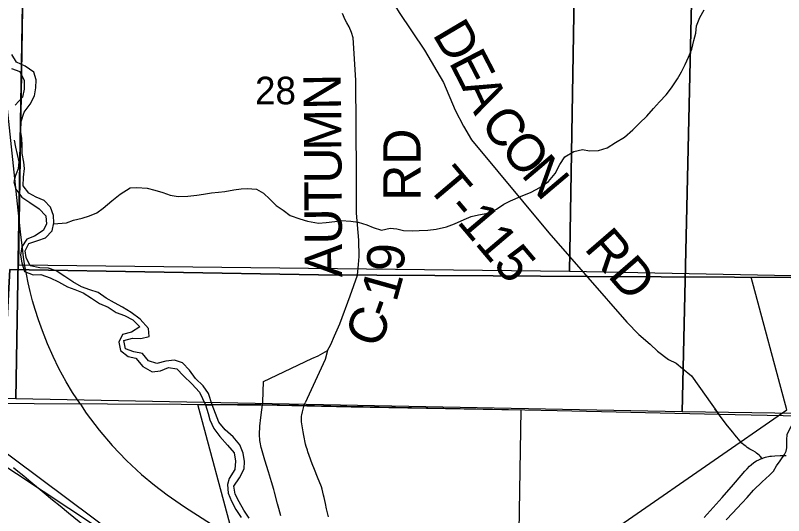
# Model space of a CAD drawing. Extents: x -19.9 to 41.9, y 0 to 32.3.
# Drawn here: x 5.034 to 6.203, y 17.59 to 18.35 of the extents above; entities that cross this region are included whole.
import ezdxf

# ---------------------------------------------------------------- set-up
doc = ezdxf.new("R2010")
doc.units = 0
for name, color, linetype in [('GM_X_City_Street', 7, 'Continuous'), ('GM_X_Corporation', 7, 'Continuous'), ('GM_X_County', 7, 'Continuous'), ('GM_X_County_Road', 7, 'Continuous'), ('GM_X_County_Road_Text', 7, 'Continuous'), ('GM_X_Major_River', 7, 'Continuous'), ('GM_X_Minor_River', 7, 'Continuous'), ('GM_X_Rail_Line', 7, 'Continuous'), ('GM_X_Section', 7, 'Continuous'), ('GM_X_Section_Text', 7, 'Continuous'), ('GM_X_State_Route', 7, 'Continuous'), ('GM_X_Township_Road', 7, 'Continuous'), ('GM_X_Township_Road_Text', 7, 'Continuous'), ('SH_Text', 7, 'Continuous')]:
    doc.layers.add(name, color=color, linetype=linetype)

msp = doc.modelspace()

# ---------------------------------------------------------------- linework, layer by layer
at = {"layer": 'GM_X_City_Street'}
for points in [[(5.4382, 17.5896), (5.4349, 17.6006), (5.4331, 17.6075), (5.4285, 17.6252), (5.4271, 17.6297), (5.4237, 17.6412), (5.4193, 17.6562), (5.4138, 17.674), (5.4085, 17.6919), (5.4081, 17.6935), (5.4064, 17.7012), (5.4061, 17.7039), (5.4057, 17.7131), (5.4061, 17.7256), (5.4078, 17.7391), (5.4108, 17.7622)], [(5.5106, 17.588), (5.509, 17.594), (5.5076, 17.6001), (5.5058, 17.6084), (5.5039, 17.6175), (5.5031, 17.6209), (5.5008, 17.6299), (5.4997, 17.6336), (5.4937, 17.648), (5.489, 17.6599), (5.4856, 17.6687), (5.4809, 17.6813), (5.4792, 17.6866), (5.4784, 17.689), (5.4767, 17.6946), (5.4756, 17.6986), (5.473, 17.7117), (5.472, 17.7173), (5.4696, 17.7322), (5.4693, 17.7347), (5.4695, 17.7408), (5.4699, 17.7427), (5.4708, 17.7477), (5.4717, 17.7516), (5.4728, 17.7554), (5.4741, 17.7591), (5.4749, 17.7612)]]:
    msp.add_lwpolyline(points, dxfattribs=at)
at = {"layer": 'GM_X_Corporation'}
for points in [[(8.9, 17.8974), (8.9, 20.9), (2.1, 20.9), (2.1, 17.918), (2.4715, 17.9106), (2.973, 17.9007), (3.7505, 17.884), (3.984, 17.879), (4.2613, 17.8672), (4.9169, 17.8392), (5.0192, 17.8403), (5.0257, 17.9637), (5.4954, 17.9559), (5.761, 17.9543), (5.9048, 17.9534), (6.2397, 17.9517), (6.2497, 17.9517), (6.3069, 17.9505), (6.7, 17.9422), (6.9468, 17.937), (7.3858, 17.9277), (7.5529, 17.9242), (7.9072, 17.9171)], [(5.0551, 18.9965), (5.8941, 18.9811), (5.8771, 17.961), (5.0393, 17.9703), (5.0537, 18.8813)], [(5.8941, 18.9811), (6.9135, 18.9637), (6.8905, 17.9411), (5.8771, 17.961)], [(2.1, 17.918), (2.1, 14.1), (8.9, 14.1), (8.9, 17.8974), (7.9072, 17.9171), (7.5529, 17.9242), (7.3858, 17.9277), (6.9468, 17.937), (6.7, 17.9422), (6.3069, 17.9505), (6.2497, 17.9517), (6.2397, 17.9517), (5.9048, 17.9534), (5.761, 17.9543), (5.4954, 17.9559), (5.0257, 17.9637), (5.0192, 17.8403), (4.9169, 17.8392), (4.2613, 17.8672), (3.984, 17.879), (3.7505, 17.884), (2.973, 17.9007), (2.4715, 17.9106)]]:
    msp.add_lwpolyline(points, close=True, dxfattribs=at)
for points in [[(2.973, 17.9007), (3.7505, 17.884), (3.984, 17.879), (4.2613, 17.8672), (4.9169, 17.8392), (5.0192, 17.8403), (5.0257, 17.9637), (5.4954, 17.9559), (5.761, 17.9543), (5.9048, 17.9534), (6.2397, 17.9517), (6.2497, 17.9517), (6.3069, 17.9505), (6.7, 17.9422), (6.9468, 17.937), (7.3858, 17.9277), (7.5529, 17.9242), (7.9072, 17.9171), (7.9208, 18.3004), (7.9387, 18.9418), (7.9433, 19.1981), (7.9567, 19.9408), (7.9833, 20.9), (2.1, 20.9)], [(7.9012, 17.4524), (7.9072, 17.9171), (7.5529, 17.9242), (7.3858, 17.9277), (6.9468, 17.937), (6.7, 17.9422), (6.3069, 17.9505), (6.2497, 17.9517), (6.2397, 17.9517), (5.9048, 17.9534), (5.761, 17.9543), (5.4954, 17.9559), (5.0257, 17.9637), (5.0192, 17.8403), (4.9169, 17.8392), (4.2613, 17.8672), (3.984, 17.879), (3.7505, 17.884), (2.973, 17.9007), (2.4715, 17.9106), (2.1, 17.918), (2.1, 14.1)], [(5.8562, 17.5075), (6.2079, 17.7506), (6.1536, 17.9521), (6.2743, 17.9513), (6.3872, 17.9486), (6.6452, 17.9441), (6.6403, 17.6667), (6.6627, 17.6004), (6.7437, 17.602), (6.7663, 17.604), (6.776, 17.6074), (6.7848, 17.6135), (6.8042, 17.6347), (6.8543, 17.709), (6.8558, 17.6308), (6.8557, 17.4298)], [(5.3659, 17.5571), (5.3116, 17.7586), (5.4323, 17.7578), (5.5452, 17.7551), (5.8032, 17.7506), (5.7983, 17.4732)]]:
    msp.add_lwpolyline(points, dxfattribs=at)
at = {"layer": 'GM_X_County'}
msp.add_lwpolyline([(8.9, 17.6915), (8.8006, 17.694), (8.0736, 17.7036), (7.0652, 17.7237), (6.7109, 17.7307), (6.5438, 17.7343), (6.1048, 17.7436), (5.8581, 17.7488), (5.4649, 17.757), (5.4078, 17.7582), (5.3977, 17.7582), (5.0628, 17.7599), (4.9191, 17.7608), (4.6534, 17.7624), (4.1838, 17.7703), (4.1772, 17.6468), (4.0749, 17.6457), (3.4193, 17.6737), (3.142, 17.6855), (2.9085, 17.6906), (2.1311, 17.7073), (2.1, 17.7079)], dxfattribs=at)
at = {"layer": 'GM_X_County_Road'}
msp.add_lwpolyline([(5.4108, 17.7622), (5.4117, 17.7934), (5.485, 17.8284), (5.4949, 17.8328), (5.5089, 17.8409), (5.5138, 17.8497), (5.5194, 17.8628), (5.5279, 17.8812), (5.5434, 17.9238), (5.5545, 17.9554), (5.5561, 17.9715), (5.557, 17.9836), (5.5566, 18.0083), (5.5529, 18.0493), (5.5529, 18.1087), (5.5523, 18.2517), (5.5479, 18.316), (5.5456, 18.3241), (5.5418, 18.3329), (5.5386, 18.339), (5.5353, 18.3446), (5.5333, 18.3497), (5.532, 18.3532)], dxfattribs=at)
at = {"layer": 'GM_X_Major_River'}
msp.add_line((5.3234, 17.7584), (5.3334, 17.7583), dxfattribs=at)
for points in [[(5.3334, 17.7583), (5.3277, 17.7754), (5.3196, 17.787), (5.308, 17.7982), (5.299, 17.8106), (5.2886, 17.8222), (5.276, 17.8258), (5.2631, 17.8244), (5.2491, 17.8208), (5.2368, 17.8248), (5.2275, 17.836), (5.2142, 17.8388), (5.2019, 17.8435), (5.1994, 17.856), (5.2123, 17.8593), (5.2249, 17.8591), (5.2377, 17.862), (5.2368, 17.8741), (5.224, 17.8883), (5.2102, 17.8987), (5.1971, 17.9068), (5.1852, 17.9131), (5.1722, 17.9205), (5.1599, 17.929), (5.1472, 17.933), (5.135, 17.9373), (5.1216, 17.9451), (5.1093, 17.9532), (5.0962, 17.9617), (5.0844, 17.9661), (5.0714, 17.9663), (5.0569, 17.9694), (5.0507, 17.9819), (5.049, 17.9921), (5.0545, 18.0032), (5.0681, 18.008), (5.0798, 18.012), (5.0899, 18.0227), (5.0927, 18.0349), (5.0922, 18.0459), (5.0878, 18.0588), (5.0781, 18.0689), (5.0659, 18.0736), (5.0544, 18.0799), (5.0462, 18.0911), (5.0464, 18.104), (5.0481, 18.1173), (5.0471, 18.1272), (5.0446, 18.1404), (5.0444, 18.1522), (5.0439, 18.1628), (5.0418, 18.1757), (5.0431, 18.189), (5.0474, 18.2031), (5.0567, 18.2154), (5.0634, 18.2277), (5.0651, 18.2402), (5.0656, 18.252), (5.062, 18.2637), (5.0489, 18.273), (5.0359, 18.2788), (5.0289, 18.2909)], [(5.0281, 18.2696), (5.0407, 18.2649), (5.0474, 18.2513), (5.0476, 18.238), (5.0451, 18.2258), (5.0339, 18.2135)], [(5.0325, 18.1603), (5.0342, 18.1497), (5.0367, 18.1388), (5.0395, 18.1274), (5.0386, 18.1168), (5.0342, 18.1068), (5.0317, 18.0973), (5.0349, 18.086), (5.0438, 18.074), (5.0561, 18.0655), (5.0703, 18.0562), (5.0804, 18.0454), (5.0814, 18.0329), (5.0766, 18.0233), (5.0634, 18.0147), (5.0517, 18.01), (5.0439, 17.9985), (5.0422, 17.9859), (5.0439, 17.9738), (5.048, 17.9606), (5.0613, 17.9558), (5.0731, 17.9564), (5.0869, 17.951), (5.0999, 17.9451), (5.1133, 17.9377), (5.1248, 17.9337), (5.1374, 17.9286), (5.1501, 17.9201), (5.162, 17.912), (5.1751, 17.9065), (5.1877, 17.8983), (5.2, 17.894), (5.213, 17.8874), (5.2234, 17.8765), (5.2106, 17.8687), (5.197, 17.8651), (5.1915, 17.8532), (5.194, 17.8408), (5.2059, 17.8315), (5.2174, 17.829), (5.2282, 17.8163), (5.242, 17.8081), (5.2549, 17.8099), (5.267, 17.815), (5.28, 17.8129), (5.2897, 17.8021), (5.3024, 17.7902), (5.3144, 17.7775), (5.3234, 17.7584)], [(5.3234, 17.7584), (5.3275, 17.7448), (5.33, 17.7356), (5.3359, 17.7224), (5.3452, 17.71), (5.3568, 17.6969), (5.3671, 17.6852), (5.3692, 17.6723), (5.3678, 17.6598), (5.3593, 17.6464), (5.3567, 17.6369), (5.358, 17.624), (5.3631, 17.6116), (5.3697, 17.5991), (5.3778, 17.5867)], [(5.39, 17.5857), (5.3815, 17.5981), (5.3745, 17.6105), (5.3687, 17.6222), (5.3666, 17.6347), (5.3752, 17.6474), (5.3823, 17.6607), (5.3825, 17.6721), (5.3808, 17.6846), (5.3757, 17.6975), (5.3657, 17.7095), (5.3534, 17.7204), (5.3438, 17.7316), (5.3334, 17.7583)]]:
    msp.add_lwpolyline(points, dxfattribs=at)
at = {"layer": 'GM_X_Minor_River'}
for points in [[(5.0923, 18.0332), (5.1121, 18.035), (5.1227, 18.0389), (5.136, 18.0421), (5.147, 18.0456), (5.1579, 18.0502), (5.1678, 18.0571), (5.181, 18.0682), (5.1938, 18.0782), (5.2089, 18.0878), (5.2188, 18.0883), (5.2344, 18.0873), (5.2462, 18.0844), (5.2583, 18.081), (5.2698, 18.077), (5.2816, 18.0748), (5.2964, 18.0753), (5.31, 18.0769), (5.3203, 18.0785), (5.3324, 18.0805), (5.343, 18.0814), (5.3529, 18.0822), (5.3666, 18.085), (5.3776, 18.0866), (5.387, 18.0871), (5.4011, 18.0861), (5.4114, 18.0797), (5.4214, 18.0707), (5.4309, 18.0613), (5.4413, 18.0541), (5.452, 18.0459), (5.4668, 18.0407), (5.4786, 18.0374), (5.4954, 18.0345), (5.5067, 18.0353), (5.52, 18.037), (5.5295, 18.0382), (5.5443, 18.0372), (5.5554, 18.0357), (5.5687, 18.0317), (5.5786, 18.0276), (5.5912, 18.0235), (5.6041, 18.0267), (5.6143, 18.0256), (5.6246, 18.0234), (5.6379, 18.0228), (5.6485, 18.0232), (5.6614, 18.0237), (5.6743, 18.025), (5.6899, 18.0285), (5.7024, 18.0332), (5.7168, 18.0401), (5.7274, 18.0444), (5.7387, 18.0468), (5.7528, 18.0496), (5.766, 18.0554), (5.7773, 18.0634), (5.7872, 18.0681), (5.8027, 18.075), (5.819, 18.0816), (5.8318, 18.0886), (5.845, 18.0974), (5.8552, 18.11), (5.8623, 18.1237), (5.8702, 18.1352), (5.8838, 18.1433), (5.8967, 18.1461), (5.9077, 18.1442), (5.9214, 18.1447), (5.9342, 18.1487), (5.9471, 18.1567), (5.9607, 18.1648), (5.9735, 18.1763), (5.9837, 18.1863), (5.9946, 18.197), (6.0051, 18.2085), (6.0138, 18.2188), (6.024, 18.2295), (6.0322, 18.2402), (6.0412, 18.2536), (6.0476, 18.2643), (6.0532, 18.2753), (6.058, 18.2867), (6.0633, 18.2989), (6.0662, 18.3122), (6.0695, 18.3233), (6.0705, 18.3343), (6.0754, 18.3469), (6.0817, 18.3587)], [(6.1152, 17.5833), (6.1257, 17.5938), (6.1316, 17.6007), (6.1398, 17.6092), (6.1473, 17.6173), (6.157, 17.6285), (6.17, 17.6409), (6.1813, 17.651), (6.1876, 17.6575), (6.192, 17.6652), (6.1976, 17.6729), (6.2043, 17.6829), (6.2069, 17.6879), (6.2075, 17.6929), (6.2075, 17.6986), (6.2078, 17.7043), (6.2084, 17.7135), (6.2145, 17.7252), (6.2281, 17.7408)]]:
    msp.add_lwpolyline(points, dxfattribs=at)
at = {"layer": 'GM_X_Rail_Line'}
for points in [[(5.1331, 17.7592), (5.1211, 17.7767), (5.1115, 17.7931), (5.1005, 17.8134), (5.0915, 17.8317), (5.0831, 17.8507), (5.0753, 17.8705), (5.0691, 17.8876), (5.0641, 17.9031), (5.0603, 17.9164), (5.0567, 17.9304), (5.0535, 17.9434), (5.0511, 17.9566), (5.0486, 17.9696), (5.0466, 17.9828), (5.0448, 17.9968), (5.0425, 18.0167), (5.04, 18.0398), (5.0376, 18.0638), (5.0204, 18.2273)], [(5.1331, 17.7592), (5.1421, 17.7453), (5.1618, 17.7195), (5.1813, 17.6965), (5.2032, 17.6736), (5.2258, 17.6523), (5.2459, 17.636), (5.2652, 17.6213), (5.2915, 17.6033), (5.3794, 17.5471), (5.5519, 17.4382), (5.6139, 17.3981), (5.6569, 17.3711), (5.6955, 17.3459), (5.7263, 17.3245), (5.7764, 17.2849), (5.8267, 17.2457), (5.8558, 17.2245)]]:
    msp.add_lwpolyline(points, dxfattribs=at)
at = {"layer": 'GM_X_Section'}
for points in [[(4.2131, 18.8031), (5.0521, 18.7876), (5.0351, 17.7675), (4.1973, 17.7768), (4.2117, 18.6878)], [(5.0521, 18.7876), (6.0716, 18.7702), (6.0485, 17.7476), (5.0351, 17.7675)], [(6.0716, 18.7702), (7.1021, 18.7492), (7.0709, 17.7326), (6.0485, 17.7476)]]:
    msp.add_lwpolyline(points, close=True, dxfattribs=at)
at = {"layer": 'GM_X_State_Route'}
msp.add_line((5.0311, 17.6628), (5.0355, 17.6592), dxfattribs=at)
for points in [[(6.0817, 17.587), (6.1095, 17.6174), (6.1264, 17.637), (6.1382, 17.6507), (6.144, 17.6573), (6.1472, 17.6609), (6.151, 17.6647), (6.1536, 17.6671), (6.1576, 17.6703), (6.1613, 17.6728), (6.1653, 17.6747), (6.1682, 17.676), (6.1702, 17.6768), (6.1723, 17.6775), (6.1754, 17.6785), (6.1817, 17.6799), (6.1844, 17.6803), (6.1893, 17.6807), (6.1974, 17.6809), (6.2066, 17.681)], [(5.0355, 17.6592), (5.0468, 17.6501), (5.0575, 17.6413)], [(5.0575, 17.6413), (5.0749, 17.627), (5.0908, 17.6139), (5.1022, 17.6045)], [(5.1022, 17.6045), (5.1148, 17.594), (5.1502, 17.5655), (5.151, 17.5648)]]:
    msp.add_lwpolyline(points, dxfattribs=at)
at = {"layer": 'GM_X_Township_Road'}
for points in [[(5.5899, 18.4006), (5.6178, 18.3543), (5.6564, 18.2971), (5.6856, 18.2481), (5.7031, 18.2059), (5.716, 18.182), (5.728, 18.1608), (5.8459, 18.0198), (5.9641, 17.8837), (5.9827, 17.8652), (6, 17.8502), (6.0108, 17.8395), (6.0275, 17.8269), (6.0395, 17.8215), (6.0491, 17.8132), (6.0628, 17.8024), (6.105, 17.743)], [(5.5089, 17.8409), (5.5053, 17.8269), (5.4749, 17.7612)], [(6.1702, 17.6768), (6.1673, 17.68), (6.1656, 17.6817), (6.1618, 17.6849), (6.1599, 17.6862), (6.1563, 17.6883), (6.1516, 17.691), (6.1476, 17.6934), (6.1453, 17.6951), (6.1429, 17.6969), (6.1394, 17.6999), (6.1363, 17.7033), (6.1341, 17.706), (6.1316, 17.709), (6.1287, 17.7126), (6.1254, 17.7166), (6.1174, 17.7264), (6.1061, 17.7411), (6.1005, 17.7483), (6.0979, 17.7518)]]:
    msp.add_lwpolyline(points, dxfattribs=at)
at = {"layer": 'SH_Text'}
msp.add_lwpolyline([(2.8043, 19.3392), (5.2749, 17.495), (2.4893, 19.3392)], close=True, dxfattribs=at)

# ---------------------------------------------------------------- texts
at = {"layer": 'GM_X_County_Road_Text'}
for s, height, rotation, p in [('N', 0.0568, 90.8927, (5.5298, 18.207)), ('M', 0.0568, 90.3293, (5.5302, 18.1447)), ('RD', 0.05682, 90, (5.6505, 18.0683)), ('U', 0.0568, 90.3169, (5.5305, 18.0947)), ('T', 0.0568, 90.3229, (5.5307, 18.0522)), ('U', 0.0568, 90.3169, (5.531, 18.0022)), ('A', 0.0568, 90.3206, (5.5313, 17.9522)), ('9', 0.0568, 87.3888, (5.6251, 17.9602)), ('1', 0.0568, 74.3673, (5.6135, 17.9129)), ('-', 0.0568, 70.3299, (5.6044, 17.887)), ('C', 0.0568, 68.5626, (5.5868, 17.842))]:
    msp.add_text(s, height=height, rotation=rotation, dxfattribs=at).set_placement(p)
at = {"layer": 'GM_X_Section_Text'}
msp.add_text('28', height=0.04186, rotation=0, dxfattribs=at).set_placement((5.3987, 18.215))
at = {"layer": 'GM_X_Township_Road_Text'}
for s, height, rotation, p in [('D', 0.0568, 300.5596, (5.6678, 18.3215)), ('E', 0.0568, 297.4074, (5.6928, 18.2792)), ('A', 0.0568, 295.2486, (5.7121, 18.242)), ('C', 0.0568, 306.4909, (5.7397, 18.1863)), ('O', 0.0568, 310.2263, (5.7699, 18.1456)), ('N', 0.0568, 310.2369, (5.8022, 18.1075)), ('T-115', 0.05682, 310.2363, (5.6584, 18.0904)), ('RD', 0.05682, 310.8148, (5.8981, 17.9954))]:
    msp.add_text(s, height=height, rotation=rotation, dxfattribs=at).set_placement(p)

doc.saveas('drawing.dxf')
